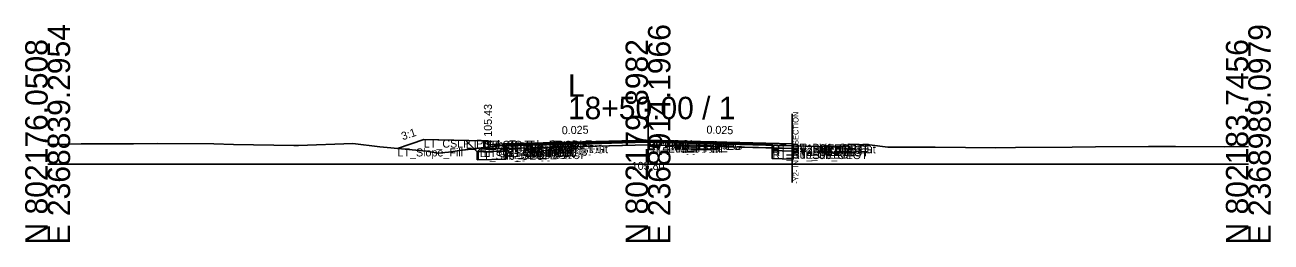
# Model space of a CAD drawing. Extents: x -26 to 8153, y -10 to 9520.
# Drawn here: x 997.2 to 1152.8, y -9.7 to 17.4 of the extents above; entities that cross this region are included whole.
import ezdxf

# ---------------------------------------------------------------- set-up
doc = ezdxf.new("R2010")
doc.units = 0
for name, color, linetype in [('Exist CMT Pavement', 7, 'Continuous'), ('Exist Cross Section Cell', 7, 'Continuous'), ('Exist XS Center Line Elevation Label', 7, 'Continuous'), ('Exist XS Ground Line', 7, 'Continuous'), ('Prop CMT Conc Surface', 7, 'Continuous'), ('Prop CMT Concrete Structures', 7, 'Continuous'), ('Prop CMT Pvmt Course 1', 7, 'Continuous'), ('Prop CMT Pvmt Course 1 CG', 7, 'Continuous'), ('Prop CMT Pvmt Course 1 Wedge', 7, 'Continuous'), ('Prop CMT Pvmt Course 2', 7, 'Continuous'), ('Prop CMT Pvmt Course 2 Wedge', 7, 'Continuous'), ('Prop CMT Pvmt Course 3', 7, 'Continuous'), ('Prop CMT Pvmt Course 3 Wedge', 7, 'Continuous'), ('Prop CMT Pvmt Surface', 7, 'Continuous'), ('Prop CMT Pvmt Wedge Surface 1', 7, 'Continuous'), ('Prop CMT Pvmt Wedge Surface 2', 7, 'Continuous'), ('Prop CMT Pvmt Wedge Surface 3', 7, 'Continuous'), ('Prop CMT Shallow Undercut', 7, 'Continuous'), ('Prop CMT Shallow Undercut Boundary', 7, 'Continuous'), ('Prop CMT Shear Line', 7, 'Continuous'), ('Prop CMT Slope Grass', 7, 'Continuous'), ('Prop CMT Subgrade Earthwork', 7, 'Continuous'), ('Prop XS Earthwork Shape', 7, 'Continuous'), ('Prop XS Hydro Elevations', 7, 'Continuous'), ('Prop XS SE Text', 7, 'Continuous'), ('Prop XS Side Slope Text', 7, 'Continuous'), ('Prop XS Subgrade Earthwork', 7, 'Continuous'), ('Scratch_Level_2', 7, 'Continuous'), ('Scratch_Level_6', 7, 'Continuous')]:
    doc.layers.add(name, color=color, linetype=linetype)

msp = doc.modelspace()

# ---------------------------------------------------------------- linework, layer by layer
at = {"layer": 'Exist CMT Pavement'}
for p, q in [((1057.26, 2.39), (1068.02, 2.54)), ((1068.02, 2.54), (1075.22, 2.81)), ((1075.22, 2.81), (1094.63, 2.26))]:
    msp.add_line(p, q, dxfattribs=at)
at = {"layer": 'Exist Cross Section Cell'}
for p, q in [((1075, 0), (1075, 8.42)), ((1000, 0), (1075, 0)), ((1075, 0), (1150, 0))]:
    msp.add_line(p, q, dxfattribs=at)
at = {"layer": 'Exist XS Ground Line'}
for p, q in [((1000, 2.46), (1000.73, 2.47)), ((1000.73, 2.47), (1004.17, 2.56)), ((1004.17, 2.56), (1010.74, 2.57)), ((1010.74, 2.57), (1013.7, 2.59)), ((1013.7, 2.59), (1020.76, 2.57)), ((1020.76, 2.57), (1023.22, 2.48)), ((1023.22, 2.48), (1030.77, 2.36)), ((1030.77, 2.36), (1031.35, 2.36)), ((1031.35, 2.36), (1038.14, 2.59)), ((1038.14, 2.59), (1041.5, 2.16)), ((1041.5, 2.16), (1044.65, 1.9)), ((1044.65, 1.9), (1047.31, 1.63)), ((1047.31, 1.63), (1048.73, 1.38)), ((1050.09, 1.52), (1051.45, 1.72)), ((1051.45, 1.72), (1054.5, 2.09)), ((1054.5, 2.09), (1057.26, 2.39)), ((1057.26, 2.39), (1068.02, 2.54)), ((1068.02, 2.54), (1075.22, 2.81)), ((1075.22, 2.81), (1094.63, 2.26)), ((1094.63, 2.26), (1097.87, 2.19)), ((1097.87, 2.19), (1098.31, 2.18)), ((1098.31, 2.18), (1099.61, 2.14)), ((1099.61, 2.14), (1100.14, 2.5)), ((1100.14, 2.5), (1102.67, 2.41)), ((1102.67, 2.41), (1104.96, 2.13)), ((1104.96, 2.13), (1110.88, 2.12)), ((1110.88, 2.12), (1118.46, 2.06)), ((1118.46, 2.06), (1120.89, 2.08)), ((1120.89, 2.08), (1127.99, 2.14)), ((1127.99, 2.14), (1130.91, 2.17)), ((1130.91, 2.17), (1137.51, 2.21)), ((1137.51, 2.21), (1140.92, 2.22)), ((1140.92, 2.22), (1147.04, 2.19)), ((1147.04, 2.19), (1150, 2.21)), ((1048.73, 1.38), (1050.09, 1.52))]:
    msp.add_line(p, q, dxfattribs=at)
at = {"layer": 'Prop CMT Conc Surface'}
for points in [[(1055, 2.43), (1055, 2.93), (1054.5, 2.93)], [(1057, 2.56), (1055, 2.43)]]:
    msp.add_lwpolyline(points, dxfattribs=at)
at = {"layer": 'Prop CMT Concrete Structures'}
for points in [[(1057, 2.56), (1055, 2.43), (1055, 2.93), (1054.5, 2.93)], [(1054.5, 2.93), (1054.5, 1.91), (1057, 1.98)], [(1057, 1.98), (1057, 2.56)]]:
    msp.add_lwpolyline(points, dxfattribs=at)
at = {"layer": 'Prop CMT Pvmt Course 1'}
for points in [[(1075, 3.01), (1057, 2.56)], [(1057, 2.56), (1057, 2.31)], [(1057, 2.31), (1057.26, 2.32)], [(1057.26, 2.44), (1075, 2.88)], [(1057.26, 2.32), (1057.26, 2.44)], [(1075, 2.76), (1075, 3.01)], [(1075, 3.01), (1093, 2.56)], [(1075, 2.76), (1075, 3.01)], [(1075, 2.88), (1075, 2.76), (1075, 2.76)], [(1090.53, 2.5), (1075, 2.88)], [(1075, 2.88), (1075, 2.76), (1075, 2.76)], [(1090.53, 2.37), (1090.53, 2.5)], [(1093, 2.31), (1090.53, 2.37)], [(1093, 2.56), (1093, 2.31)]]:
    msp.add_lwpolyline(points, dxfattribs=at)
at = {"layer": 'Prop CMT Pvmt Course 1 CG'}
for points in [[(1057, 1.98), (1054, 1.9), (1053.66, 1.56)], [(1053.66, 1.56), (1057, 1.65)], [(1057, 1.65), (1057, 1.98)]]:
    msp.add_lwpolyline(points, dxfattribs=at)
at = {"layer": 'Prop CMT Pvmt Course 1 Wedge'}
for points in [[(1075, 2.88), (1057.26, 2.44)], [(1075, 2.88), (1090.53, 2.5)]]:
    msp.add_lwpolyline(points, dxfattribs=at)
at = {"layer": 'Prop CMT Pvmt Course 2'}
for points in [[(1057.26, 2.32), (1057, 2.31)], [(1057, 2.31), (1057, 1.98)], [(1057, 1.98), (1057.26, 1.99)], [(1057.26, 1.99), (1057.26, 2.32)], [(1090.53, 2.04), (1090.53, 2.37)], [(1090.53, 2.37), (1093, 2.31)], [(1093, 1.98), (1090.53, 2.04)], [(1093, 2.31), (1093, 1.98)]]:
    msp.add_lwpolyline(points, dxfattribs=at)
at = {"layer": 'Prop CMT Pvmt Course 2 Wedge'}
for points in [[(1075, 2.76), (1057.26, 2.32)], [(1075, 2.76), (1090.53, 2.37)]]:
    msp.add_lwpolyline(points, dxfattribs=at)
at = {"layer": 'Prop CMT Pvmt Course 3'}
for points in [[(1057.26, 1.99), (1057, 1.98)], [(1057, 1.98), (1057, 1.65)], [(1057, 1.65), (1057.26, 1.65)], [(1057.26, 1.65), (1057.26, 1.99)], [(1090.53, 2.04), (1093, 1.98)], [(1090.53, 1.71), (1090.53, 2.04)], [(1093, 1.65), (1090.53, 1.71)], [(1093, 1.98), (1093, 1.65)]]:
    msp.add_lwpolyline(points, dxfattribs=at)
at = {"layer": 'Prop CMT Pvmt Course 3 Wedge'}
for points in [[(1075, 2.43), (1057.26, 1.99)], [(1075, 2.43), (1090.53, 2.04)]]:
    msp.add_lwpolyline(points, dxfattribs=at)
at = {"layer": 'Prop CMT Pvmt Surface'}
for points in [[(1075, 3.01), (1057, 2.56)], [(1075, 3.01), (1093, 2.56), (1093, 2.3)]]:
    msp.add_lwpolyline(points, dxfattribs=at)
at = {"layer": 'Prop CMT Pvmt Wedge Surface 1'}
for points in [[(1057, 2.31), (1057, 2.56)], [(1057.26, 2.32), (1057, 2.31)], [(1075, 2.88), (1057.26, 2.44)], [(1057.26, 2.44), (1057.26, 2.32)], [(1075, 2.88), (1090.53, 2.5)], [(1090.53, 2.5), (1090.53, 2.37)], [(1090.53, 2.37), (1093, 2.31)], [(1093, 2.31), (1093, 2.56)]]:
    msp.add_lwpolyline(points, dxfattribs=at)
at = {"layer": 'Prop CMT Pvmt Wedge Surface 2'}
for points in [[(1075, 2.76), (1057, 2.31)], [(1057, 2.31), (1057, 2.56)], [(1075, 2.76), (1093, 2.31)], [(1093, 2.31), (1093, 2.56)]]:
    msp.add_lwpolyline(points, dxfattribs=at)
at = {"layer": 'Prop CMT Pvmt Wedge Surface 3'}
for points in [[(1057, 1.98), (1057, 2.56)], [(1075, 2.43), (1057, 1.98)], [(1075, 2.43), (1093, 1.98)], [(1093, 1.98), (1093, 2.56)]]:
    msp.add_lwpolyline(points, dxfattribs=at)
at = {"layer": 'Prop CMT Shallow Undercut'}
for p, q in [((1057.26, 1.65), (1053.66, 1.56)), ((1053.66, 1.56), (1053.66, 0.56)), ((1057.26, 0.65), (1057.26, 1.65)), ((1093, 1.65), (1090.53, 1.71)), ((1090.53, 1.71), (1090.53, 0.71)), ((1093, 0.65), (1093, 1.65)), ((1053.66, 0.56), (1057.26, 0.65)), ((1090.53, 0.71), (1093, 0.65))]:
    msp.add_line(p, q, dxfattribs=at)
at = {"layer": 'Prop CMT Shallow Undercut Boundary'}
for p, q in [((1053.66, 1.56), (1057.26, 1.65)), ((1053.66, 1.56), (1053.66, 0.56)), ((1057.26, 1.65), (1057.26, 0.65)), ((1090.53, 1.71), (1090.53, 0.71)), ((1090.53, 1.71), (1093, 1.65)), ((1093, 1.65), (1093, 0.65)), ((1053.66, 0.56), (1057.26, 0.65)), ((1093, 0.65), (1090.53, 0.71))]:
    msp.add_line(p, q, dxfattribs=at)
at = {"layer": 'Prop CMT Shear Line'}
msp.add_line((1093, -2.26), (1093, 6.3), dxfattribs=at)
at = {"layer": 'Prop CMT Slope Grass'}
msp.add_lwpolyline([(1054.5, 2.93), (1047, 3.08), (1043.71, 1.98)], dxfattribs=at)
at = {"layer": 'Prop CMT Subgrade Earthwork'}
for points in [[(1057, 1.65), (1053.66, 1.56), (1052.25, 2.97)], [(1057.26, 1.65), (1057, 1.65)], [(1057.26, 1.65), (1057.28, 2.39)], [(1090.53, 1.71), (1090.53, 2.37)], [(1090.53, 1.71), (1093, 1.65)]]:
    msp.add_lwpolyline(points, dxfattribs=at)
at = {"layer": 'Prop XS Earthwork Shape'}
for points in [[(1043.71, 1.98), (1044.65, 1.9), (1047.31, 1.63), (1048.73, 1.38), (1050.09, 1.52), (1051.45, 1.72), (1053.28, 1.94), (1052.25, 2.97), (1047, 3.08)], [(1057.26, 2.39), (1057.28, 2.39), (1057.26, 1.65), (1057, 1.65), (1053.66, 1.56), (1053.28, 1.94), (1054.5, 2.09)], [(1057.26, 1.65), (1057.26, 0.65), (1053.66, 0.56), (1053.66, 1.56), (1057, 1.65)], [(1093, 0.65), (1090.53, 0.71), (1090.53, 1.71), (1093, 1.65)]]:
    msp.add_lwpolyline(points, close=True, dxfattribs=at)
at = {"layer": 'Prop XS Subgrade Earthwork'}
for p, q in [((1053.66, 1.56), (1057.26, 1.65)), ((1090.53, 1.71), (1093, 1.65))]:
    msp.add_line(p, q, dxfattribs=at)
at = {"layer": 'Scratch_Level_6'}
for p, q in [((1057.26, 1.65), (1053.66, 1.56)), ((1053.66, 1.56), (1053.66, 0.56)), ((1057.26, 0.65), (1057.26, 1.65)), ((1093, 1.65), (1090.53, 1.71)), ((1090.53, 1.71), (1090.53, 0.71)), ((1093, 0.65), (1093, 1.65)), ((1053.66, 0.56), (1057.26, 0.65)), ((1090.53, 0.71), (1093, 0.65))]:
    msp.add_line(p, q, dxfattribs=at)

# ---------------------------------------------------------------- texts
at = {"layer": 'Exist Cross Section Cell'}
for s, p in [('E 2368839.2954', (1002.8, -10)), ('E 2368914.1966', (1077.8, -10)), ('E 2368989.0979', (1152.8, -10)), ('N 802176.0508', (1000, -10)), ('N 802179.8982', (1075, -10)), ('N 802183.7456', (1150, -10))]:
    msp.add_text(s, height=2.8, rotation=90, dxfattribs=at).set_placement(p)
for s, p in [('L', (1065, 8.42)), ('18+50.00 / 1', (1065, 5.62))]:
    msp.add_text(s, height=2.8, dxfattribs=at).set_placement(p)
at = {"layer": 'Exist XS Center Line Elevation Label'}
msp.add_text('105.80', height=1, dxfattribs=at).set_placement((1072.97, -0.7))
at = {"layer": 'Prop CMT Shear Line'}
msp.add_text('-Y2- INTERSECTION', height=0.7, rotation=90, dxfattribs=at).set_placement((1093.8, -2.43))
at = {"layer": 'Prop XS Hydro Elevations'}
msp.add_text('105.43', height=1, rotation=90, dxfattribs=at).set_placement((1055.5, 3.43))
at = {"layer": 'Prop XS SE Text'}
for rotation, p in [(1.4321, (1064.24, 3.74)), (358.5679, (1082.29, 3.83))]:
    msp.add_text('0.025', height=1, rotation=rotation, dxfattribs=at).set_placement(p)
at = {"layer": 'Prop XS Side Slope Text'}
msp.add_text('3:1', height=1, rotation=18.4349, dxfattribs=at).set_placement((1044.37, 2.99))
at = {"layer": 'Scratch_Level_2'}
for s, p in [('LT_Slope_Fill', (1043.71, 0.98)), ('LT_CSLP_Pnt', (1047, 2.08)), ('LT_Sub_Trench_Out_DLT', (1052.25, 1.97)), ('LT_Sub_OEOP', (1053.66, 0.56)), ('LT_CG1_Shelf_Out', (1054, 0.9)), ('LT_CG_Top_BOC', (1054.5, 1.93)), ('LT_CG_Bot_BOC', (1054.5, 0.91)), ('LT_CG_Top_Face', (1055, 1.93)), ('LT_CG_Top_Gut', (1055, 1.43)), ('LT_PV1_OEOT', (1057, 1.56)), ('LT_PV2_OEOT', (1057, 1.31)), ('LT_PV3_OEOT', (1057, 0.98)), ('LT_CG_Bot_IE', (1057, 0.98)), ('LT_Sub_OEOT', (1057, 0.65)), ('LT_PV1_OEEOP', (1057.26, 1.44)), ('LT_PV_OEEOP_EG', (1057.26, 1.39)), ('LT_PV2_OEEOP', (1057.26, 1.32)), ('LT_PV3_OEEOP', (1057.26, 0.99)), ('LT_Sub_OEEOP', (1057.26, 0.65)), ('LT_PV_Sub_Tie_Out', (1057.28, 1.39)), ('PV1_PGL', (1075, 2.01)), ('RT_PV1_IEEOP', (1075, 1.88)), ('LT_PV1_IEEOP', (1075, 1.88)), ('RT_PV_IEEOP_EG', (1075, 1.8)), ('LT_PV_IEEOP_EG', (1075, 1.8)), ('RT_PV2_IEEOP', (1075, 1.76)), ('LT_PV2_IEEOP', (1075, 1.76)), ('PV2_PGL', (1075, 1.76)), ('RT_PV3_IEEOP', (1075, 1.43)), ('LT_PV3_IEEOP', (1075, 1.43)), ('RT_PV_Sub_Tie_Out', (1090.51, 1.37)), ('RT_PV1_OEEOP', (1090.53, 1.5)), ('RT_PV_OEEOP_EG', (1090.53, 1.37)), ('RT_PV2_OEEOP', (1090.53, 1.37)), ('RT_PV3_OEEOP', (1090.53, 1.04)), ('RT_Sub_OEEOP', (1090.53, 0.71)), ('RT_PV1_OEOT', (1093, 1.56)), ('RT_PV2_OEOT', (1093, 1.31)), ('RT_PV3_OEOT', (1093, 0.98)), ('RT_Sub_OEOT', (1093, 0.65))]:
    msp.add_text(s, height=1, dxfattribs=at).set_placement(p)

doc.saveas('drawing.dxf')
